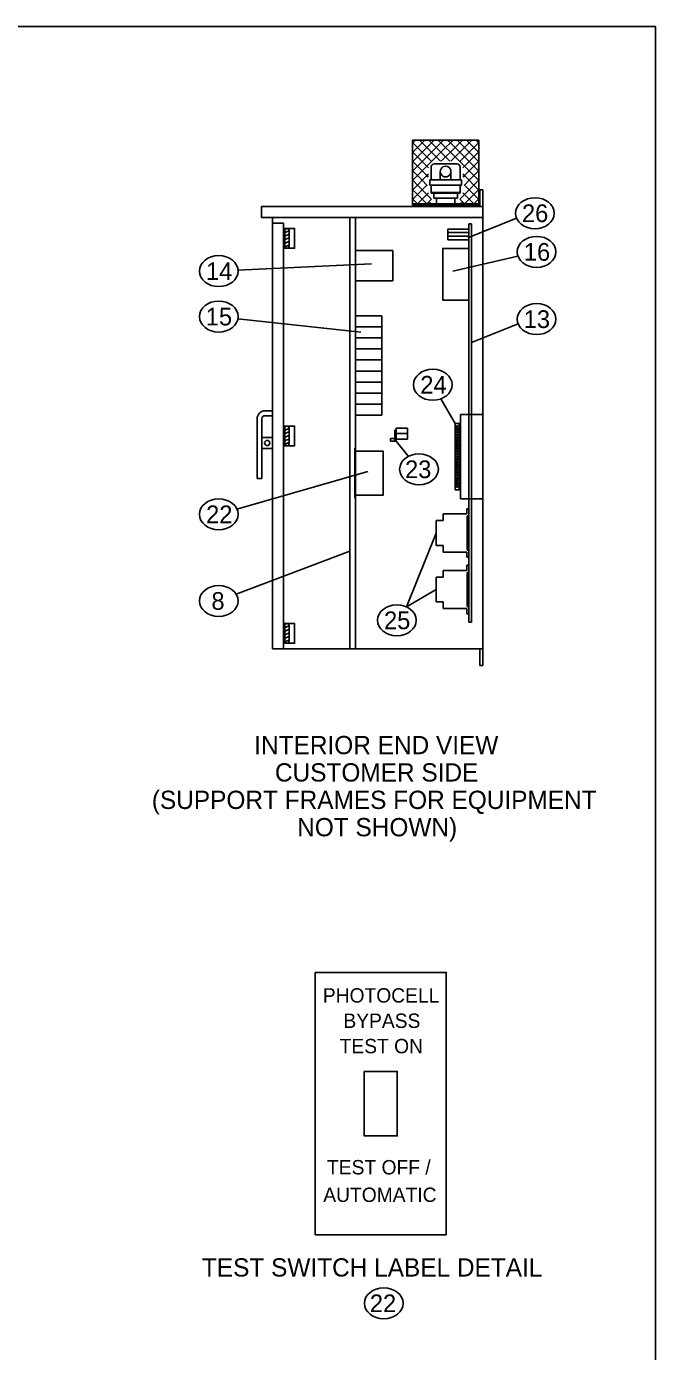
# Model space of a CAD drawing. Extents: x 99862 to 103680, y 99470 to 105076.
# Drawn here: x 102582 to 103151, y 103878 to 105076 of the extents above; entities that cross this region are included whole.
import ezdxf

# ---------------------------------------------------------------- set-up
doc = ezdxf.new("R2010")
doc.units = 0
for name, color, linetype in [('Level 1', 7, 'Continuous'), ('Level 15', 7, 'Continuous'), ('Level 20', 7, 'Continuous'), ('Level 40', 7, 'Continuous'), ('Level 60', 7, 'Continuous')]:
    doc.layers.add(name, color=color, linetype=linetype)

msp = doc.modelspace()

# ---------------------------------------------------------------- linework, layer by layer
at = {"layer": 'Level 1'}
for p, q in [((102931.3, 104972.9), (102991.3, 104972.9)), ((102931.3, 104915.2), (102931.3, 104972.9)), ((102931.3, 104970.7), (102931.5, 104970.5)), ((102931.5, 104970.5), (102931.3, 104970.3)), ((102931.5, 104970.5), (102934, 104972.9)), ((102935.8, 104966.2), (102931.5, 104970.5)), ((102931.5, 104962), (102935.8, 104966.2)), ((102940, 104970.5), (102935.8, 104966.2)), ((102935.8, 104966.2), (102940, 104962)), ((102940, 104970.5), (102937.6, 104972.9)), ((102942.5, 104972.9), (102940, 104970.5)), ((102944.3, 104966.2), (102940, 104970.5)), ((102940, 104962), (102944.3, 104966.2)), ((102948.5, 104970.5), (102944.3, 104966.2)), ((102944.3, 104966.2), (102948.5, 104962)), ((102946.1, 104972.9), (102948.5, 104970.5)), ((102948.5, 104970.5), (102951, 104972.9)), ((102952.8, 104966.2), (102948.5, 104970.5)), ((102948.5, 104962), (102952.8, 104966.2)), ((102957, 104970.5), (102952.8, 104966.2)), ((102952.8, 104966.2), (102957, 104962)), ((102954.6, 104972.9), (102957, 104970.5)), ((102957, 104970.5), (102959.5, 104972.9)), ((102961.3, 104966.2), (102957, 104970.5)), ((102957, 104962), (102961.3, 104966.2)), ((102965.6, 104970.5), (102961.3, 104966.2)), ((102961.3, 104966.2), (102965.6, 104962)), ((102963.1, 104972.9), (102965.6, 104970.5)), ((102965.6, 104970.5), (102968, 104972.9)), ((102969.8, 104966.2), (102965.6, 104970.5)), ((102965.6, 104962), (102969.8, 104966.2)), ((102974.1, 104970.5), (102969.8, 104966.2)), ((102969.8, 104966.2), (102974.1, 104962)), ((102971.6, 104972.9), (102974.1, 104970.5)), ((102974.1, 104970.5), (102976.5, 104972.9)), ((102978.3, 104966.2), (102974.1, 104970.5)), ((102974.1, 104962), (102978.3, 104966.2)), ((102982.6, 104970.5), (102978.3, 104966.2)), ((102978.3, 104966.2), (102982.6, 104962)), ((102980.1, 104972.9), (102982.6, 104970.5)), ((102985, 104972.9), (102982.6, 104970.5)), ((102982.6, 104970.5), (102986.8, 104966.2)), ((102986.8, 104966.2), (102982.6, 104962)), ((102986.8, 104966.2), (102991.1, 104970.5)), ((102991.1, 104962), (102986.8, 104966.2)), ((102991.1, 104970.5), (102988.6, 104972.9)), ((102991.3, 104970.7), (102991.1, 104970.5)), ((102991.1, 104970.5), (102991.3, 104970.3)), ((102991.3, 104915.2), (102991.3, 104972.9)), ((102931.3, 104962.2), (102931.5, 104962)), ((102931.5, 104962), (102931.3, 104961.8)), ((102931.3, 104953.7), (102931.5, 104953.5)), ((102935.8, 104957.7), (102931.5, 104962)), ((102931.5, 104953.5), (102935.8, 104957.7)), ((102940, 104962), (102935.8, 104957.7)), ((102935.8, 104957.7), (102940, 104953.5)), ((102944.3, 104957.7), (102940, 104962)), ((102940, 104953.5), (102944.3, 104957.7)), ((102948.5, 104962), (102944.3, 104957.7)), ((102944.3, 104957.7), (102948.5, 104953.5)), ((102952.8, 104957.7), (102948.5, 104962)), ((102948.5, 104953.5), (102952.8, 104957.7)), ((102957, 104962), (102952.8, 104957.7)), ((102952.8, 104957.7), (102956.7, 104953.8)), ((102961.3, 104957.7), (102957, 104962)), ((102957.4, 104953.8), (102961.3, 104957.7)), ((102965.6, 104962), (102961.3, 104957.7)), ((102961.3, 104957.7), (102965.2, 104953.8)), ((102969.8, 104957.7), (102965.6, 104962)), ((102965.9, 104953.8), (102969.8, 104957.7)), ((102974.1, 104962), (102969.8, 104957.7)), ((102969.8, 104957.7), (102974.1, 104953.5)), ((102978.3, 104957.7), (102974.1, 104962)), ((102974.1, 104953.5), (102978.3, 104957.7)), ((102982.6, 104962), (102978.3, 104957.7)), ((102978.3, 104957.7), (102982.6, 104953.5)), ((102982.6, 104962), (102986.8, 104957.7)), ((102986.8, 104957.7), (102982.6, 104953.5)), ((102986.8, 104957.7), (102991.1, 104962)), ((102991.1, 104953.5), (102986.8, 104957.7)), ((102991.3, 104962.2), (102991.1, 104962)), ((102991.1, 104962), (102991.3, 104961.8)), ((102991.3, 104953.7), (102991.1, 104953.5)), ((102931.5, 104953.5), (102931.3, 104953.2)), ((102931.3, 104945.2), (102931.5, 104945)), ((102931.5, 104945), (102931.3, 104944.7)), ((102935.8, 104949.2), (102931.5, 104953.5)), ((102931.5, 104945), (102935.8, 104949.2)), ((102935.8, 104940.7), (102931.5, 104945)), ((102940, 104953.5), (102935.8, 104949.2)), ((102935.8, 104949.2), (102940, 104945)), ((102940, 104945), (102935.8, 104940.7)), ((102944.3, 104949.2), (102940, 104953.5)), ((102940, 104945), (102944.3, 104949.2)), ((102944.3, 104940.7), (102940, 104945)), ((102948.5, 104953.5), (102944.3, 104949.2)), ((102944.3, 104949.2), (102945.7, 104947.8)), ((102945.7, 104942.1), (102944.3, 104940.7)), ((102948.1, 104937), (102948.1, 104948.2)), ((102948.8, 104953.3), (102948.5, 104953.5)), ((102951.3, 104951.4), (102971.3, 104951.4)), ((102956.5, 104937), (102956.5, 104944.4)), ((102966.1, 104937), (102966.1, 104944.4)), ((102974.1, 104953.5), (102973.8, 104953.3)), ((102978.3, 104949.2), (102974.1, 104953.5)), ((102974.5, 104937), (102974.5, 104948.2)), ((102976.9, 104947.8), (102978.3, 104949.2)), ((102978.3, 104940.7), (102976.9, 104942.1)), ((102982.6, 104953.5), (102978.3, 104949.2)), ((102978.3, 104949.2), (102982.6, 104945)), ((102982.6, 104945), (102978.3, 104940.7)), ((102982.6, 104953.5), (102986.8, 104949.2)), ((102986.8, 104949.2), (102982.6, 104945)), ((102982.6, 104945), (102986.8, 104940.7)), ((102986.8, 104949.2), (102991.1, 104953.5)), ((102991.1, 104945), (102986.8, 104949.2)), ((102986.8, 104940.7), (102991.1, 104945)), ((102991.1, 104953.5), (102991.3, 104953.2)), ((102991.3, 104945.2), (102991.1, 104945)), ((102991.1, 104945), (102991.3, 104944.7)), ((102931.3, 104936.7), (102931.5, 104936.5)), ((102931.5, 104936.5), (102931.3, 104936.2)), ((102931.5, 104936.5), (102935.8, 104940.7)), ((102935.8, 104932.2), (102931.5, 104936.5)), ((102931.5, 104927.9), (102935.8, 104932.2)), ((102935.8, 104940.7), (102940, 104936.5)), ((102940, 104936.5), (102935.8, 104932.2)), ((102935.8, 104932.2), (102940, 104927.9)), ((102940, 104936.5), (102944.3, 104940.7)), ((102944.3, 104932.2), (102940, 104936.5)), ((102940, 104927.9), (102944.3, 104932.2)), ((102944.3, 104940.7), (102945.6, 104939.4)), ((102944.5, 104932.4), (102944.3, 104932.2)), ((102944.3, 104932.2), (102944.5, 104932)), ((102948.1, 104937), (102946.9, 104937)), ((102946.9, 104937), (102946.9, 104932.2)), ((102946.9, 104932.2), (102975.7, 104932.2)), ((102974.5, 104937), (102948.1, 104937)), ((102948.1, 104932.2), (102948.1, 104925)), ((102974.5, 104937), (102975.7, 104937)), ((102974.5, 104932.2), (102974.5, 104925)), ((102975.7, 104937), (102975.7, 104932.2)), ((102977, 104939.4), (102978.3, 104940.7)), ((102978.3, 104932.2), (102978.1, 104932.4)), ((102978.1, 104932), (102978.3, 104932.2)), ((102978.3, 104940.7), (102982.6, 104936.5)), ((102982.6, 104936.5), (102978.3, 104932.2)), ((102978.3, 104932.2), (102982.6, 104927.9)), ((102986.8, 104940.7), (102982.6, 104936.5)), ((102982.6, 104936.5), (102986.8, 104932.2)), ((102986.8, 104932.2), (102982.6, 104927.9)), ((102991.1, 104936.5), (102986.8, 104940.7)), ((102986.8, 104932.2), (102991.1, 104936.5)), ((102991.1, 104927.9), (102986.8, 104932.2)), ((102991.3, 104936.7), (102991.1, 104936.5)), ((102991.1, 104936.5), (102991.3, 104936.2)), ((102931.3, 104928.2), (102931.5, 104927.9)), ((102931.5, 104927.9), (102931.3, 104927.7)), ((102931.3, 104919.7), (102931.5, 104919.4)), ((102931.5, 104919.4), (102931.3, 104919.2)), ((102935.8, 104923.7), (102931.5, 104927.9)), ((102931.5, 104919.4), (102935.8, 104923.7)), ((102935.8, 104915.2), (102931.5, 104919.4)), ((102940, 104927.9), (102935.8, 104923.7)), ((102935.8, 104923.7), (102940, 104919.4)), ((102940, 104919.4), (102935.8, 104915.2)), ((102944.3, 104923.7), (102940, 104927.9)), ((102940, 104919.4), (102944.3, 104923.7)), ((102944.3, 104915.2), (102940, 104919.4)), ((102945.7, 104925.1), (102944.3, 104923.7)), ((102944.3, 104923.7), (102948.2, 104919.7)), ((102948.4, 104919.3), (102944.3, 104915.2)), ((102974.5, 104925.6), (102948.1, 104925.6)), ((102974.5, 104925), (102948.1, 104925)), ((102950.5, 104920.8), (102950.5, 104925)), ((102971.5, 104920.2), (102951.1, 104920.2)), ((102952.9, 104915.3), (102952.9, 104920.2)), ((102969.7, 104915.3), (102969.7, 104920.2)), ((102972.1, 104920.8), (102972.1, 104925)), ((102978.3, 104915.2), (102974.2, 104919.3)), ((102974.4, 104919.7), (102978.3, 104923.7)), ((102978.3, 104923.7), (102976.9, 104925.1)), ((102982.6, 104927.9), (102978.3, 104923.7)), ((102978.3, 104923.7), (102982.6, 104919.4)), ((102982.6, 104919.4), (102978.3, 104915.2)), ((102982.6, 104927.9), (102986.8, 104923.7)), ((102986.8, 104923.7), (102982.6, 104919.4)), ((102982.6, 104919.4), (102986.8, 104915.2)), ((102986.8, 104923.7), (102991.1, 104927.9)), ((102991.1, 104919.4), (102986.8, 104923.7)), ((102986.8, 104915.2), (102991.1, 104919.4)), ((102991.3, 104928.2), (102991.1, 104927.9)), ((102991.1, 104927.9), (102991.3, 104927.7)), ((102991.3, 104919.7), (102991.1, 104919.4)), ((102991.1, 104919.4), (102991.3, 104919.2)), ((102931.3, 104915.2), (102991.3, 104915.2)), ((102931.3, 104914.1), (102931.3, 104915.1)), ((102931.3, 104915.1), (102991.3, 104915.1)), ((102931.3, 104914.1), (102991.3, 104914.1)), ((102967.3, 104912.9), (102955.3, 104912.9)), ((102991.3, 104914.1), (102991.3, 104915.1)), ((102874.8, 104512.9), (102874.8, 104902.9)), ((102879.8, 104512.9), (102879.8, 104902.9)), ((102984.8, 104897), (102982.2, 104897)), ((102982.2, 104897), (102982.2, 104724.9)), ((102984.8, 104724.9), (102984.8, 104897)), ((102814.8, 104875.1), (102814.8, 104892.9)), ((102815.8, 104890.9), (102815.8, 104877.1)), ((102819.8, 104890.9), (102815.8, 104889.3)), ((102819.8, 104887.7), (102815.8, 104886.1)), ((102819.8, 104884.4), (102815.8, 104882.9)), ((102819.8, 104890.9), (102819.8, 104877.1)), ((102819.8, 104881.2), (102815.8, 104879.7)), ((102819.8, 104878), (102815.9, 104876.5)), ((102913.5, 104873), (102879.8, 104873)), ((102913.5, 104845.5), (102913.5, 104873)), ((102913.5, 104845.5), (102879.8, 104845.5)), ((102903.6, 104814.1), (102879.8, 104814.1)), ((102903.6, 104724.1), (102903.6, 104814.1)), ((102903.6, 104804.1), (102879.8, 104804.1)), ((102903.6, 104794.1), (102879.8, 104794.1)), ((102903.6, 104784.1), (102879.8, 104784.1)), ((102903.6, 104774.1), (102879.8, 104774.1)), ((102903.6, 104764.1), (102879.8, 104764.1)), ((102903.6, 104754.1), (102879.8, 104754.1)), ((102903.6, 104744.1), (102879.8, 104744.1)), ((102798.1, 104728.2), (102804.8, 104728.2)), ((102903.6, 104734.1), (102879.8, 104734.1)), ((102790.8, 104666.9), (102790.8, 104720.9)), ((102795.2, 104720.9), (102795.2, 104666.9)), ((102798.1, 104723.7), (102804.8, 104723.7)), ((102814.8, 104714.3), (102814.8, 104696.6)), ((102903.6, 104724.1), (102879.8, 104724.1)), ((102969.8, 104716.8), (102969.8, 104656.8)), ((102969.8, 104716.8), (102974.8, 104716.8)), ((102973.5, 104716.8), (102973.5, 104656.8)), ((102974.8, 104724.9), (102974.8, 104648.7)), ((102974.8, 104724.9), (102994.8, 104724.9)), ((102974.8, 104716.8), (102974.8, 104656.8)), ((102982.2, 104724.9), (102982.2, 104648.7)), ((102984.8, 104648.7), (102984.8, 104724.9)), ((102795.2, 104704.1), (102804.8, 104704.1)), ((102804.8, 104704.1), (102804.8, 104694.1)), ((102815.8, 104712.3), (102815.8, 104698.6)), ((102819.8, 104712.3), (102815.8, 104710.8)), ((102819.8, 104709.1), (102815.8, 104707.6)), ((102819.8, 104705.9), (102815.8, 104704.4)), ((102819.8, 104702.7), (102815.8, 104701.1)), ((102819.8, 104712.3), (102819.8, 104698.6)), ((102911.5, 104703.1), (102911.5, 104700.6)), ((102911.5, 104703.1), (102915.3, 104703.1)), ((102915.3, 104710.6), (102915.3, 104700.6)), ((102915.3, 104710.6), (102916.5, 104710.6)), ((102926.9, 104712.5), (102916.5, 104712.5)), ((102916.5, 104712.5), (102916.5, 104702.5)), ((102916.5, 104710.6), (102916.5, 104700.6)), ((102926.9, 104707.5), (102916.5, 104707.5)), ((102926.9, 104702.5), (102916.5, 104702.5)), ((102926.9, 104712.5), (102926.9, 104702.5)), ((102795.2, 104694.1), (102804.8, 104694.1)), ((102819.8, 104699.5), (102815.9, 104698)), ((102879.8, 104694.3), (102879.1, 104694.3)), ((102879.1, 104694.3), (102879.1, 104649.3)), ((102879.8, 104649.3), (102879.8, 104694.3)), ((102911.5, 104700.6), (102915.3, 104700.6)), ((102916.5, 104700.6), (102915.3, 104700.6)), ((102795.2, 104666.9), (102790.8, 104666.9)), ((102969.8, 104656.8), (102974.8, 104656.8)), ((102879.8, 104649.3), (102879.1, 104649.3)), ((102994.8, 104648.7), (102974.8, 104648.7)), ((102982.2, 104648.7), (102982.2, 104537)), ((102984.8, 104610.4), (102984.8, 104648.7)), ((102959.2, 104635), (102959.2, 104628.9)), ((102959.2, 104635), (102980.5, 104635)), ((102980.5, 104639.6), (102980.5, 104635)), ((102980.5, 104639.6), (102982.2, 104639.6)), ((102982.1, 104634), (102980.9, 104632.9)), ((102980.9, 104632.9), (102980.9, 104602.5)), ((102982.2, 104639.6), (102982.2, 104634)), ((102952.8, 104628.9), (102952.8, 104606.5)), ((102952.8, 104628.9), (102959.2, 104628.9)), ((102952.8, 104606.5), (102959.2, 104606.5)), ((102959.2, 104606.5), (102959.2, 104600.4)), ((102984.8, 104537), (102984.8, 104610.4)), ((102959.2, 104600.4), (102980.5, 104600.4)), ((102980.5, 104600.4), (102980.5, 104595.8)), ((102980.5, 104595.8), (102982.2, 104595.8)), ((102982.2, 104601.4), (102980.9, 104602.5)), ((102982.2, 104601.4), (102982.2, 104595.8)), ((102959.2, 104583.9), (102959.2, 104577.9)), ((102959.2, 104583.9), (102980.5, 104583.9)), ((102980.5, 104588.6), (102980.5, 104583.9)), ((102980.5, 104588.6), (102982.2, 104588.6)), ((102982.1, 104583), (102980.9, 104581.8)), ((102982.2, 104588.6), (102982.2, 104583)), ((102952.8, 104577.9), (102952.8, 104555.4)), ((102952.8, 104577.9), (102959.2, 104577.9)), ((102980.9, 104581.8), (102980.9, 104551.5)), ((102952.8, 104555.4), (102959.2, 104555.4)), ((102959.2, 104555.4), (102959.2, 104549.4)), ((102959.2, 104549.4), (102980.5, 104549.4)), ((102980.5, 104549.4), (102980.5, 104544.8)), ((102982.2, 104550.3), (102980.9, 104551.5)), ((102982.2, 104550.3), (102982.2, 104544.8)), ((102814.8, 104535.8), (102814.8, 104518)), ((102980.5, 104544.8), (102982.2, 104544.8)), ((102982.2, 104537), (102984.8, 104537)), ((102815.8, 104533.8), (102815.8, 104520)), ((102819.8, 104533.8), (102815.8, 104532.2)), ((102819.8, 104530.6), (102815.8, 104529)), ((102819.8, 104527.4), (102815.8, 104525.8)), ((102819.8, 104524.1), (102815.8, 104522.6)), ((102819.8, 104533.8), (102819.8, 104520)), ((102819.8, 104520.9), (102815.9, 104519.4))]:
    msp.add_line(p, q, dxfattribs=at)
for points in [[(99862, 102999.5), (103151, 102999.5), (103151, 105075.5), (99862, 105075.5)], [(102963.4, 104889.2), (102982.2, 104889.2), (102982.2, 104892.4), (102963.4, 104892.4)], [(102963.4, 104885.9), (102982.2, 104885.9), (102982.2, 104889.2), (102963.4, 104889.2)], [(102963.4, 104882.7), (102982.2, 104882.7), (102982.2, 104885.9), (102963.4, 104885.9)], [(102982.2, 104874.9), (102958.7, 104874.9), (102958.7, 104828.2), (102982.2, 104828.2)], [(102879.8, 104691.8), (102904.8, 104691.8), (102904.8, 104651.8), (102879.8, 104651.8)], [(102961.9, 103983.4), (102961.9, 104220.5), (102843.4, 104220.5), (102843.4, 103983.4)], [(102887.7, 104131.1), (102887.7, 104072.8), (102917.6, 104072.8), (102917.6, 104131.1)]]:
    msp.add_lwpolyline(points, close=True, dxfattribs=at)
for points in [[(102814.8, 104892.9), (102824.8, 104892.9), (102824.8, 104875.1), (102814.8, 104875.1)], [(102814.8, 104696.6), (102824.8, 104696.6), (102824.8, 104714.3), (102814.8, 104714.3)], [(102814.8, 104518), (102824.8, 104518), (102824.8, 104535.8), (102814.8, 104535.8)]]:
    msp.add_lwpolyline(points, dxfattribs=at)
for centre, radius in [((102971.7, 104713.8), 0.758), ((102971.7, 104711.3), 0.758), ((102971.7, 104708.9), 0.758), ((102971.7, 104706.4), 0.758), ((102971.7, 104704), 0.758), ((102971.7, 104701.5), 0.758), ((102800, 104699.1), 2.37), ((102971.7, 104699.1), 0.758), ((102971.7, 104696.6), 0.758), ((102971.7, 104694.2), 0.758), ((102971.7, 104691.7), 0.758), ((102971.7, 104689.3), 0.758), ((102971.7, 104686.8), 0.758), ((102971.7, 104684.4), 0.758), ((102971.7, 104681.9), 0.758), ((102971.7, 104679.5), 0.758), ((102971.7, 104677), 0.758), ((102971.7, 104674.6), 0.758), ((102971.7, 104672.1), 0.758), ((102971.7, 104669.7), 0.758), ((102971.7, 104667.2), 0.758), ((102971.7, 104664.7), 0.758), ((102971.7, 104662.3), 0.758), ((102971.7, 104659.8), 0.758)]:
    msp.add_circle(centre, radius, dxfattribs=at)
for centre, radius, start, end in [((102951.3, 104948.2), 3.21, 90, 180), ((102961.3, 104944.4), 4.81, 0, 180.0003), ((102961.3, 104944.4), 4.81, 179.9997, 360), ((102971.3, 104948.2), 3.21, 0, 90), ((102951.1, 104920.8), 0.602, 180, 270), ((102971.5, 104920.8), 0.602, 270, 0), ((102955.3, 104915.3), 2.41, 180, 270), ((102967.3, 104915.3), 2.41, 270, 0), ((102817.8, 104890.9), 2, 90, 180), ((102817.8, 104890.9), 2, 0, 90), ((102817.8, 104877.1), 2, 180, 270), ((102817.8, 104877.1), 2, 270, 0), ((102798.1, 104720.9), 7.25, 90, 180), ((102798.1, 104720.9), 2.82, 90, 180), ((102817.8, 104712.3), 2, 90, 180), ((102817.8, 104712.3), 2, 0, 90), ((102817.8, 104698.6), 2, 180, 270), ((102817.8, 104698.6), 2, 270, 0), ((102817.8, 104533.8), 2, 90, 180), ((102817.8, 104533.8), 2, 0, 90), ((102817.8, 104520), 2, 180, 270), ((102817.8, 104520), 2, 270, 0)]:
    msp.add_arc(centre, radius, start, end, dxfattribs=at)
at = {"layer": 'Level 15'}
for p, q in [((102994.8, 104927.9), (102992.3, 104927.9)), ((102992.3, 104927.9), (102992.3, 104912.9)), ((102994.8, 104902.9), (102794.8, 104902.9)), ((102804.8, 104897.9), (102814.8, 104897.9)), ((102814.8, 104512.9), (102814.8, 104897.9)), ((102981.3, 104884.4), (103025.3, 104902.4)), ((102894.4, 104860.9), (102773.6, 104855.2)), ((103026.7, 104867.9), (102967.7, 104854.4)), ((102884.7, 104799.1), (102773.5, 104811.3)), ((103026.8, 104806.7), (102984.8, 104790)), ((102969.8, 104716.8), (102957.1, 104738.9)), ((102916.5, 104700.6), (102927.6, 104687)), ((102891.1, 104673.4), (102772.6, 104639.4)), ((102952.8, 104617.7), (102926, 104550.9)), ((102772, 104562.3), (102874.8, 104601.2)), ((102952.8, 104566.8), (102926, 104550.9)), ((102992.3, 104497.9), (102992.3, 104512.9)), ((102994.8, 104497.9), (102992.3, 104497.9))]:
    msp.add_line(p, q, dxfattribs=at)
at = {"layer": 'Level 20'}
for centre in [(103042, 104906.7), (103043.5, 104871.8), (102756.2, 104854.4), (102756.2, 104813.3), (103043.5, 104811), (102949.7, 104751.7), (102937.2, 104675.3), (102756.2, 104634.6), (102756.2, 104556.3), (102917.2, 104538.8), (102905.4, 103921.5)]:
    msp.add_ellipse(centre, major_axis=(-17.5, 0), ratio=0.8, dxfattribs=at)
at = {"layer": 'Level 40'}
for p, q in [((102994.8, 104927.9), (102994.8, 104497.9)), ((102994.8, 104912.9), (102794.8, 104912.9)), ((102794.8, 104902.9), (102794.8, 104912.9)), ((102804.8, 104512.9), (102804.8, 104902.9)), ((102994.8, 104512.9), (102804.8, 104512.9))]:
    msp.add_line(p, q, dxfattribs=at)
for points in [[(102948.2, 104913.3), (102948.2, 104913.2), (102945.5, 104913.2), (102945.5, 104913.3)], [(102948.2, 104913.2), (102948.2, 104912.9), (102945.5, 104912.9), (102945.5, 104913.2)], [(102947.8, 104915.1), (102947.8, 104915.9), (102945.9, 104915.9), (102945.9, 104915.1)], [(102947.8, 104913.3), (102947.8, 104914.1), (102945.9, 104914.1), (102945.9, 104913.3)], [(102974.4, 104913.3), (102974.4, 104913.2), (102977.1, 104913.2), (102977.1, 104913.3)], [(102974.4, 104913.2), (102974.4, 104912.9), (102977.1, 104912.9), (102977.1, 104913.2)], [(102974.8, 104915.1), (102974.8, 104915.9), (102976.7, 104915.9), (102976.7, 104915.1)], [(102974.8, 104913.3), (102974.8, 104914.1), (102976.7, 104914.1), (102976.7, 104913.3)]]:
    msp.add_lwpolyline(points, close=True, dxfattribs=at)
at = {"layer": 'Level 60'}
msp.add_line((103151, 105075.5), (103151, 105075.5), dxfattribs=at)

# ---------------------------------------------------------------- texts
at = {"layer": 'Level 20'}
for s, height, p in [('26', 16, (103030.3, 104898.7)), ('16', 16, (103032, 104863.8)), ('14', 16, (102744.7, 104846.4)), ('15', 16, (102744.5, 104805.3)), ('13', 16, (103031.9, 104803)), ('24', 16, (102938.4, 104743.7)), ('23', 16, (102924.6, 104667.3)), ('22', 16, (102744.8, 104626.6)), ('8', 16, (102749.6, 104548.3)), ('25', 16, (102905.6, 104530.8)), ('INTERIOR END VIEW', 16.5, (102788.3, 104417.8)), ('CUSTOMER SIDE', 16.5, (102807, 104393.1)), ('(SUPPORT FRAMES FOR EQUIPMENT ', 16.5, (102695.7, 104368.3)), ('NOT SHOWN)', 16.5, (102827.1, 104343.6)), ('TEST SWITCH LABEL DETAIL', 16.5, (102741, 103945.7)), ('22', 16, (102892.8, 103913.5))]:
    msp.add_text(s, height=height, dxfattribs=at).set_placement(p)
at = {"layer": 'Level 40'}
for s, p in [('PHOTOCELL', (102850.3, 104193.3)), ('BYPASS', (102868.9, 104170.4)), ('TEST ON', (102865.5, 104147.5)), ('TEST OFF /', (102854.1, 104038)), ('AUTOMATIC', (102850.7, 104013.1))]:
    msp.add_text(s, height=13, dxfattribs=at).set_placement(p)

doc.saveas('drawing.dxf')
